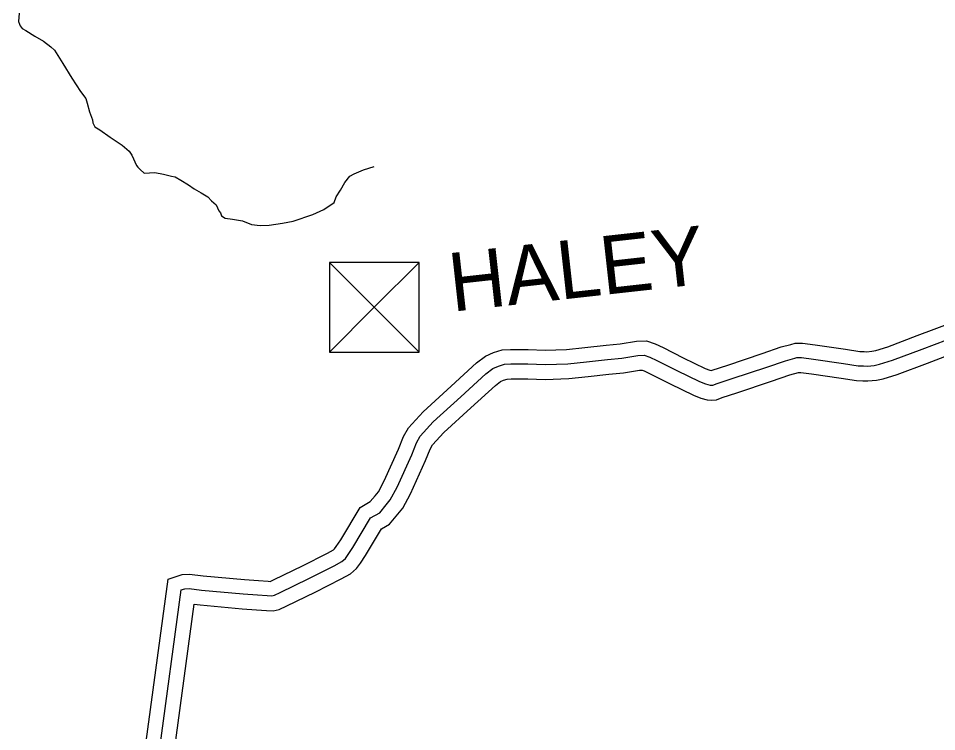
# Model space of a CAD drawing. Extents: x 1551132 to 1791609, y 378168 to 563823.
# Drawn here: x 1631391 to 1637199, y 423914 to 428427 of the extents above; entities that cross this region are included whole.
import ezdxf

# ---------------------------------------------------------------- set-up
doc = ezdxf.new("R2010")
doc.units = 0
for name, color, linetype in [('DESIGN - ROW - Right-of-Way and Easement Labels', 7, 'Continuous'), ('DESIGN - TRAFFIC CONTROL PERMANENT - Pavement Marking', 7, 'Continuous'), ('DESIGN - TRANSPORTATION - Text', 7, 'Continuous'), ('SURVEY - PROPERTY - Owners', 7, 'Continuous')]:
    doc.layers.add(name, color=color, linetype=linetype)

msp = doc.modelspace()

# ---------------------------------------------------------------- linework, layer by layer
at = {"layer": 'DESIGN - TRAFFIC CONTROL PERMANENT - Pavement Marking'}
for p, q in [((1633925.261, 426881.492), (1633359.56, 426881.478)), ((1633642.418, 426598.635), (1633359.56, 426881.478)), ((1633359.56, 426881.478), (1633359.574, 426315.777)), ((1633642.418, 426598.635), (1633925.261, 426881.492)), ((1633925.275, 426315.791), (1633925.261, 426881.492)), ((1633359.574, 426315.777), (1633642.418, 426598.635)), ((1633642.418, 426598.635), (1633925.275, 426315.791)), ((1633359.574, 426315.777), (1633925.275, 426315.791))]:
    msp.add_line(p, q, dxfattribs=at)
at = {"layer": 'DESIGN - TRANSPORTATION - Text'}
for points in [[(1631395.488, 428459.732), (1631390.972, 428407.664), (1631398.805, 428389.547), (1631402.705, 428379.489), (1631414.563, 428363.33), (1631438.437, 428349.055), (1631496.136, 428314.387), (1631549.86, 428281.77), (1631595.55, 428247.219), (1631619.35, 428224.926), (1631672.565, 428140.208), (1631729.697, 428047.422), (1631784.929, 427964.678), (1631818.52, 427920.244), (1631826.228, 427890.101), (1631841.711, 427835.833), (1631859.235, 427785.54), (1631863.044, 427765.465), (1631868.927, 427753.381), (1631874.81, 427741.289), (1631906.634, 427720.922), (1631972.249, 427676.154), (1632047.797, 427625.261), (1632091.455, 427586.735), (1632109.213, 427560.493), (1632138.604, 427496.058), (1632146.512, 427485.957), (1632160.361, 427469.782), (1632186.161, 427447.465), (1632254.243, 427450.773), (1632308.175, 427440.19), (1632360.09, 427427.631), (1632382.065, 427423.389), (1632417.889, 427402.98), (1632467.646, 427374.405), (1632503.412, 427347.987), (1632547.202, 427323.478), (1632588.976, 427296.994), (1632612.759, 427272.702), (1632642.517, 427246.335)], [(1632642.517, 427246.335), (1632658.158, 427208.092), (1632670.049, 427195.95), (1632675.874, 427177.85), (1632699.749, 427163.574), (1632745.723, 427157.082), (1632807.663, 427146.424), (1632865.461, 427121.773), (1632919.435, 427115.206), (1632977.509, 427118.615), (1633061.69, 427131.765), (1633129.847, 427143.091), (1633254.352, 427185.892), (1633322.709, 427217.251), (1633389.199, 427262.652), (1633401.532, 427296.595), (1633427.982, 427340.413), (1633456.464, 427388.214), (1633486.88, 427427.99), (1633515.046, 427443.724), (1633573.337, 427469.174), (1633641.593, 427490.517)]]:
    msp.add_lwpolyline(points, dxfattribs=at)
at = {"layer": 'SURVEY - PROPERTY - Owners'}
for points in [[(1633553.261, 425332.502), (1633617.276, 425369.444), (1633647.267, 425406.429), (1633667.958, 425431.546), (1633704.899, 425500.798), (1633796.322, 425701.911), (1633827.913, 425780.397), (1633857.971, 425836.873), (1633951.235, 425937.893), (1634129.015, 426099.18), (1634288.861, 426246.801), (1634345.193, 426289.736), (1634396.008, 426311.894), (1634450.14, 426328.562), (1634503.264, 426330.812), (1634615.762, 426331.995), (1634724.009, 426327.228), (1634859.006, 426331.904), (1634973.612, 426344.637), (1635109.017, 426359.779), (1635196.515, 426366.888), (1635300.287, 426384.414), (1635363.502, 426387.197), (1635419.834, 426367.638), (1635469.608, 426344.529), (1635595.705, 426279.186), (1635734.402, 426212.301), (1635764.61, 426200.892), (1635772.676, 426198.676), (1635780.459, 426201.609), (1635878.399, 426233.477), (1636095.985, 426305.604), (1636216.749, 426347.621), (1636277.664, 426363.947), (1636303.539, 426371.13), (1636351.129, 426370.772), (1636431.202, 426361.489), (1636622.765, 426333.73), (1636712.496, 426319.646), (1636740.12, 426318.229), (1636758.253, 426317.696), (1636789.861, 426320.596), (1636813.71, 426325.988), (1636889.967, 426349.572), (1637075.862, 426419.257), (1637308.307, 426506.768)], [(1633618.934, 425265.675), (1633677.158, 425299.268), (1633717.499, 425349.027), (1633743.723, 425380.861), (1633786.281, 425460.638), (1633879.72, 425666.186), (1633910.253, 425742.046), (1633932.544, 425783.93), (1634015.159, 425873.408), (1634190.255, 426032.27), (1634347.251, 426177.249), (1634391.475, 426210.959), (1634427.583, 426226.701), (1634465.657, 426238.426), (1634505.656, 426240.118), (1634614.245, 426241.259), (1634723.584, 426236.451), (1634865.589, 426241.368), (1634983.661, 426254.485), (1635117.733, 426269.477), (1635207.764, 426276.794), (1635309.87, 426294.036), (1635350.153, 426295.811), (1635385.777, 426283.444), (1635429.626, 426263.085), (1635555.131, 426198.042), (1635698.611, 426128.857), (1635736.502, 426114.548), (1635766.435, 426106.315), (1635775.768, 426105.182), (1635784.434, 426106.173), (1635810.492, 426115.99), (1635906.698, 426147.291), (1636125.159, 426219.71), (1636243.432, 426260.861), (1636301.53, 426276.436), (1636315.555, 426280.328), (1636345.546, 426280.103), (1636419.469, 426271.528), (1636609.232, 426244.036), (1636703.104, 426229.302), (1636736.454, 426227.585), (1636761.078, 426226.86), (1636804.069, 426230.81), (1636837.143, 426238.286), (1636919.308, 426263.695), (1637107.762, 426334.338), (1637342.339, 426422.657)], [(1633687.199, 425196.198), (1633739.406, 425226.316), (1633790.505, 425289.359), (1633822.48, 425328.168), (1633870.879, 425418.896), (1633966.418, 425629.051), (1633995.851, 425702.178), (1634010.067, 425728.896), (1634081.607, 425806.373), (1634253.92, 425962.71), (1634407.95, 426104.956), (1634439.582, 426129.065), (1634460.398, 426138.14), (1634481.79, 426144.732), (1634508.147, 426145.849), (1634612.67, 426146.94), (1634723.142, 426142.082), (1634872.439, 426147.257), (1634994.103, 426160.774), (1635126.791, 426175.608), (1635219.456, 426183.142), (1635319.837, 426200.092), (1635336.278, 426200.817), (1635350.378, 426195.917), (1635388.06, 426178.425), (1635512.957, 426113.698), (1635661.412, 426042.113), (1635707.278, 426024.788), (1635748.152, 426013.546), (1635775.443, 426010.237), (1635806.75, 426013.821), (1635841.716, 426026.988), (1635936.114, 426057.705), (1636155.484, 426130.424), (1636271.164, 426170.675), (1636326.346, 426185.467), (1636328.046, 426185.934), (1636339.746, 426185.851), (1636407.278, 426178.017), (1636595.165, 426150.792), (1636693.346, 426135.383), (1636732.645, 426133.366), (1636764.011, 426132.441), (1636818.835, 426137.475), (1636861.501, 426147.117), (1636949.807, 426174.426), (1637140.919, 426246.069), (1637377.714, 426335.222)], [(1631948.463, 421900.019), (1631958.913, 421949.662), (1632014.22, 422377.915), (1632194.009, 423806.077), (1632338.047, 424879.372), (1632427.67, 424907.632), (1632473.094, 424910.332), (1632559.842, 424900.065), (1632820.869, 424875.514), (1632910.242, 424869.922), (1632970.433, 424864.947), (1632984.016, 424864.614), (1633008.265, 424876.464), (1633187.336, 424963.2), (1633346.349, 425043.261), (1633384.74, 425064.786), (1633391.531, 425070.761), (1633401.356, 425084.962), (1633430.539, 425128.088), (1633553.261, 425332.502)], [(1632037.219, 421881.327), (1632048.411, 421934.487), (1632104.201, 422366.44), (1632283.956, 423794.377), (1632420.279, 424810.187), (1632444.253, 424817.746), (1632470.436, 424819.304), (1632550.259, 424809.854), (1632813.786, 424785.07), (1632903.676, 424779.445), (1632965.583, 424774.328), (1632994.265, 424773.628), (1633011.007, 424776.845), (1633047.947, 424794.896), (1633227.502, 424881.865), (1633388.948, 424963.15), (1633437.438, 424990.343), (1633459.788, 425009.985), (1633476.221, 425033.744), (1633507.037, 425079.287), (1633618.934, 425265.675)], [(1632129.484, 421861.901), (1632141.442, 421918.711), (1632197.733, 422354.514), (1632377.463, 423782.219), (1632503.368, 424720.452), (1632540.301, 424716.077), (1632806.428, 424691.051), (1632896.851, 424685.393), (1632960.541, 424680.126), (1633002.098, 424679.118), (1633041.123, 424686.609), (1633089.196, 424710.102), (1633269.251, 424797.312), (1633433.23, 424879.873), (1633492.22, 424912.957), (1633530.736, 424946.808), (1633554.044, 424980.501), (1633586.56, 425028.56), (1633687.199, 425196.198)]]:
    msp.add_lwpolyline(points, dxfattribs=at)

# ---------------------------------------------------------------- texts
at = {"layer": 'DESIGN - ROW - Right-of-Way and Easement Labels'}
msp.add_text('HALEY', height=369.9916, rotation=6.3400778, dxfattribs=at).set_placement((1634134.906, 426570.409))

doc.saveas('drawing.dxf')
